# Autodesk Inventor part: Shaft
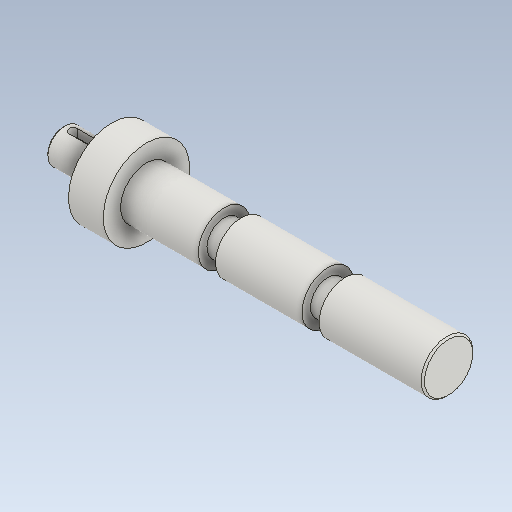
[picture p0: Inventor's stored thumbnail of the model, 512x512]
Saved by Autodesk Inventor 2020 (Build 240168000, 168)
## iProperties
CustomPartVersion: 1
Created: 2019-09
Part Number: Shaft
Material: Steel
Document SubType Name: Modeling
Designer: user
Density: 7.85 g/cm^3
Appearance: Steel
Mass: 160.494 g
Surface Area: 66.0555 cm^2
Volume: 20.4451 cm^3
Length: 111,560 mm
Author: user
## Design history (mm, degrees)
sketch "Main Sketch"
  geometry: L1 (0, 0)-(111.56, 0) reference; L2 (0, 0)-(0, 5); L3 (0, 5)-(14, 5); L4 (14, 5)-(14, 12.5); L5 (24.06, 12.5)-(24.06, 7.5); L6 (14, 12.5)-(24.06, 12.5); L7 (46.56, 7.5)-(46.56, 5); L8 (24.06, 7.5)-(46.56, 7.5); L9 (46.56, 5)-(51.56, 5); L10 (51.56, 5)-(51.56, 7.5); L11 (76.56, 7.5)-(76.56, 5); L12 (51.56, 7.5)-(76.56, 7.5); L13 (76.56, 5)-(81.56, 5); L14 (81.56, 5)-(81.56, 7.5); L15 (111.56, 7.5)-(111.56, 0); L16 (81.56, 7.5)-(111.56, 7.5)
  constraints: 32 end point, 9 horizontal, 8 vertical
  dimensions: "d3" = 10 diameter of L3 L1 (derived); "d4" = 25 diameter of L6 L1 (derived); "d5" = 15 diameter of L8 L1 (derived); "d6" = 10 diameter of L9 L1 (derived); "d7" = 15 diameter of L12 L1 (derived); "d8" = 10 diameter of L13 L1 (derived); "d9" = 15 diameter of L16 L1 (derived)
revolve "Revolution1" sketch "Main Sketch" stored, may be unused: angle "d10" = 0 deg
chamfer "Chamfer1" distance "d11" = 0.5; stored, may be unused: second distance "d12" = 0.5, angle "d13" = 45 deg
node "Keyway1"
chamfer "Chamfer2" distance "d14" = 0.5; stored, may be unused: second distance "d15" = 0.5, angle "d16" = 45 deg
body "Solid1"
feature "iFeature3:1"
other parameters: "d0" = 0, "d1" = 0, "d2" = 0, "Length" = 111.56 [user parameter]
